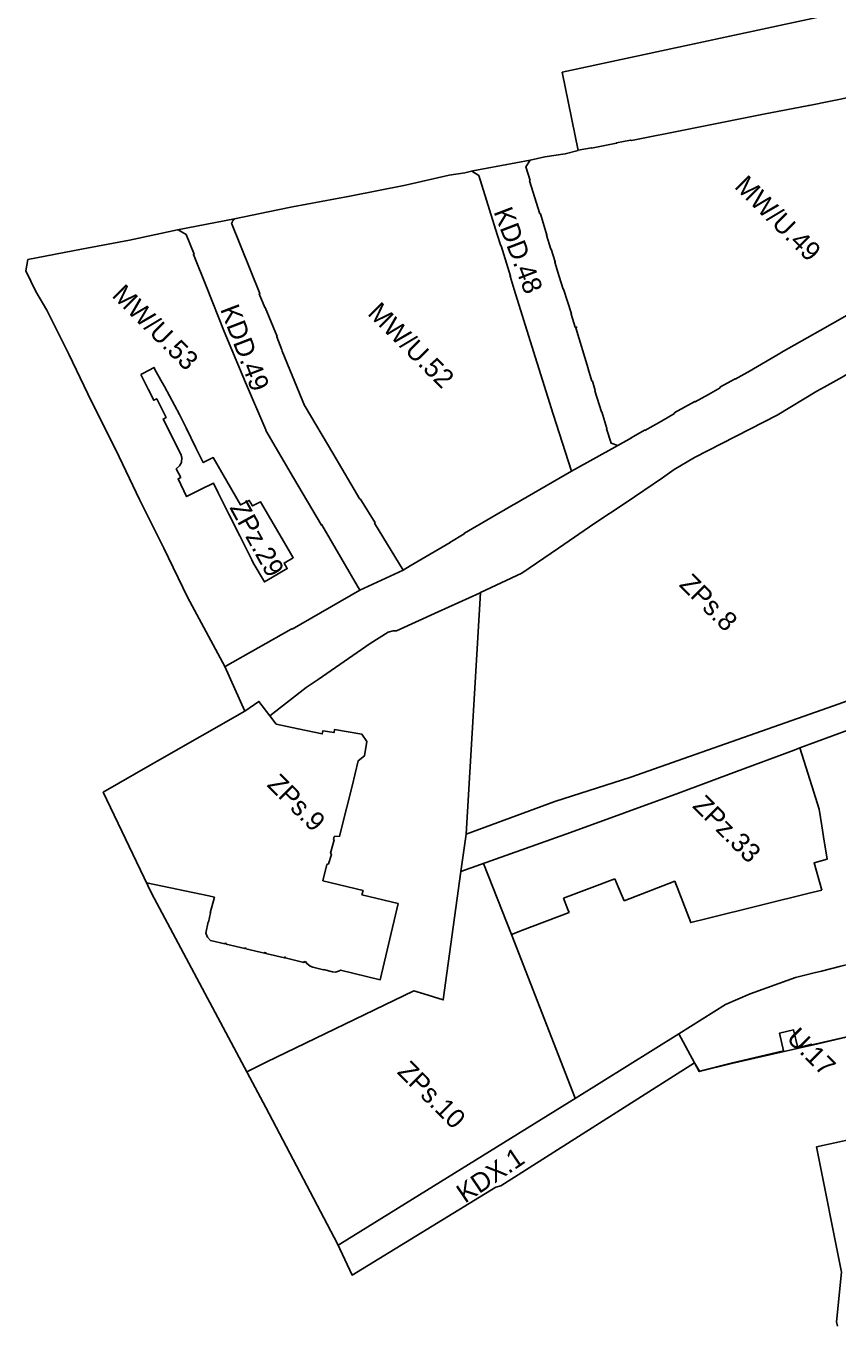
# Model space of a CAD drawing. Extents: x 7423835 to 7425280, y 5546086 to 5547600.
# Drawn here: x 7423835.1 to 7424089, y 5546198.3 to 5546605 of the extents above; entities that cross this region are included whole.
import ezdxf

# ---------------------------------------------------------------- set-up
doc = ezdxf.new("R2010")
doc.units = 0
for name, color, linetype in [('linie rozgraniczające', 7, 'Continuous'), ('nieprzekraczalne linie zabudowy', 7, 'Continuous'), ('obowiazujace linie zabudowy', 7, 'Continuous'), ('przeznaczenia terenów', 7, 'Continuous')]:
    doc.layers.add(name, color=color, linetype=linetype)

msp = doc.modelspace()

# ---------------------------------------------------------------- linework, layer by layer
at = {"layer": 'linie rozgraniczające'}
for p, q in [((7424002.95, 5546590.54), (7424101.85, 5546611.78)), ((7424007.94, 5546566.05), (7424002.95, 5546590.54)), ((7424005.85, 5546465.72), (7424020.34, 5546473.74)), ((7423939.54, 5546428.46), (7423953.14, 5546434.8)), ((7423897.44, 5546404.64), (7423897.34, 5546404.59)), ((7424077.32, 5546379.16), (7424075.54, 5546378.49)), ((7423987.03, 5546320.75), (7423978.35, 5546342.99)), ((7424006.98, 5546269.52), (7423987.03, 5546320.75)), ((7424044.41, 5546280.59), (7424039.51, 5546289.67)), ((7424007.29, 5546269.71), (7423933.34, 5546223.86)), ((7423933.34, 5546223.86), (7423932.8, 5546223.54))]:
    msp.add_line(p, q, dxfattribs=at)
for points in [[(7424007.92, 5546566.13), (7424007.92, 5546566.13), (7424012.08, 5546566.94), (7424012.12, 5546566.8), (7424019.99, 5546568.34), (7424019.98, 5546568.48), (7424024.36, 5546569.34), (7424024.63, 5546569.25), (7424042.46, 5546572.74), (7424065.98, 5546577.41), (7424080.17, 5546580.17), (7424080.29, 5546580.16), (7424093.65, 5546582.86), (7424110.6, 5546586.22), (7424110.68, 5546586.29), (7424125.36, 5546591.15), (7424125.56, 5546591.27), (7424140.15, 5546601.52), (7424140.07, 5546601.67), (7424144.53, 5546604.8)], [(7424091.83, 5546288.66), (7424081.26, 5546286.15), (7424076.53, 5546285.07), (7424071.54, 5546283.94), (7424056.01, 5546280.41), (7424045.88, 5546277.87), (7424044.41, 5546280.59), (7423983.72, 5546242.11), (7423982.18, 5546241.75), (7423937.14, 5546214.2), (7423932.61, 5546223.95), (7423910.19, 5546266.66), (7423874.37, 5546333.67), (7423859.24, 5546365.27), (7423873.99, 5546373.73), (7423876.16, 5546374.97), (7423903.56, 5546390.64), (7423897.35, 5546404.58), (7423885.67, 5546426.36), (7423878.26, 5546441.63), (7423870.62, 5546456.9), (7423863.21, 5546472.44), (7423855.6, 5546487.51), (7423848.47, 5546502.36), (7423841.57, 5546516.12), (7423838.18, 5546521.94), (7423835.06, 5546528.47), (7423835.65, 5546531.92), (7423852.44, 5546535.15), (7423867.52, 5546538.02), (7423882.5, 5546541.21), (7423900.36, 5546544.64), (7423913.95, 5546547.52), (7423918.55, 5546548.42), (7423936.42, 5546551.83), (7423953.84, 5546555.27), (7423967.51, 5546558.31), (7423972.43, 5546559.13), (7423974.95, 5546559.68), (7423992.97, 5546563.05), (7423997.49, 5546564.05), (7424003.93, 5546565.01), (7424007.94, 5546566.05)], [(7423992.87, 5546563.03), (7423991.54, 5546561), (7423992.91, 5546556.69), (7423992.75, 5546556.62), (7423995.97, 5546546.27), (7423996.12, 5546546.3), (7423998.19, 5546539.63), (7423998.04, 5546539.59), (7423999.39, 5546535.2), (7423999.53, 5546535.23), (7424000.77, 5546531.23), (7424000.62, 5546531.18), (7424002.02, 5546526.65), (7424003.26, 5546522.68), (7424003.39, 5546522.7), (7424005.84, 5546514.93), (7424005.71, 5546514.87), (7424006.98, 5546510.75), (7424007.39, 5546510.87), (7424007.47, 5546510.62), (7424007.2, 5546510.54), (7424011.13, 5546497.85), (7424011.05, 5546497.8), (7424012.24, 5546493.91), (7424012.4, 5546493.95), (7424013.31, 5546490.98), (7424013.2, 5546490.9), (7424015.24, 5546484.27), (7424015.41, 5546484.33), (7424016.97, 5546479.08), (7424016.84, 5546479.03), (7424018.25, 5546474.51), (7424020.34, 5546473.74)], [(7423974.7, 5546559.63), (7423976.9, 5546558.21), (7423982.6, 5546539.81), (7423983.71, 5546536.19), (7423983.86, 5546536.24), (7423986.79, 5546526.79), (7423986.64, 5546526.75), (7423987.92, 5546522.6), (7423993.46, 5546504.88), (7424000.11, 5546483.56), (7424005.85, 5546465.72), (7423987.99, 5546455.41), (7423987.81, 5546455.33), (7423987.65, 5546455.24), (7423972.41, 5546446.36), (7423972.3, 5546446.13), (7423967.77, 5546443.47), (7423967.84, 5546443.37), (7423967.84, 5546443.37), (7423961.59, 5546439.73), (7423955.35, 5546436.09), (7423953.14, 5546434.8), (7423944.22, 5546449.45), (7423944.35, 5546449.61), (7423940.15, 5546456.46), (7423939.73, 5546457.09)], [(7423939.73, 5546457.09), (7423939.62, 5546457.02), (7423931.12, 5546471.4), (7423922.43, 5546485.98), (7423922.28, 5546486.32), (7423915.3, 5546503.3), (7423915.17, 5546503.66), (7423913.56, 5546507.77), (7423913.67, 5546507.85), (7423909.99, 5546516.98), (7423909.86, 5546516.94), (7423908.11, 5546521.26), (7423908.28, 5546521.34), (7423899.46, 5546543.38), (7423899.59, 5546543.44), (7423899.67, 5546544.03)], [(7423900.15, 5546544.6), (7423900.12, 5546544.42), (7423899.81, 5546544.21), (7423899.67, 5546544.03)], [(7423882.74, 5546541.26), (7423885.24, 5546539.77), (7423887.67, 5546533.63), (7423887.51, 5546533.57), (7423891.59, 5546523.4), (7423897.15, 5546509.47), (7423903.84, 5546493.45), (7423910.13, 5546478.69), (7423910.19, 5546478.47), (7423918.77, 5546463.62), (7423927.54, 5546448.86), (7423927.72, 5546448.95), (7423939.54, 5546428.46), (7423918.37, 5546416.31), (7423918.29, 5546416.45), (7423918.09, 5546416.31), (7423897.44, 5546404.64)], [(7424095.99, 5546516.73), (7424083.68, 5546509.71), (7424071.51, 5546502.83), (7424071.39, 5546502.79), (7424061.02, 5546496.74), (7424060.84, 5546496.63), (7424057.15, 5546494.55), (7424057.08, 5546494.68), (7424052.31, 5546491.97), (7424052.38, 5546491.83), (7424048.71, 5546489.76), (7424044.58, 5546487.43), (7424044.51, 5546487.56), (7424038.05, 5546483.96), (7424038.13, 5546483.8), (7424034.04, 5546481.4), (7424028.82, 5546478.49), (7424028.72, 5546478.61), (7424024.56, 5546476.22), (7424024.61, 5546476.12), (7424020.34, 5546473.74)], [(7424097.06, 5546498.96), (7424090.64, 5546495.12), (7424084.98, 5546492.05), (7424082.63, 5546490.76), (7424070.3, 5546483.21), (7424044.42, 5546470.01), (7424038.04, 5546466.26), (7424034.35, 5546463.61), (7424022.62, 5546455.76), (7424013.13, 5546449.48), (7424001.74, 5546441.67), (7423990.34, 5546433.85), (7423977.36, 5546427.73)], [(7423977.36, 5546427.73), (7423977.08, 5546427.6), (7423964.07, 5546421.71), (7423951.06, 5546415.82), (7423949.98, 5546415.78), (7423948.42, 5546415.34), (7423942.83, 5546411.83), (7423926.5, 5546400.57), (7423922.81, 5546398.02), (7423911.44, 5546389.18), (7423907.98, 5546393.72), (7423903.56, 5546390.64)], [(7423977.36, 5546427.73), (7423972.84, 5546352.13), (7423971.23, 5546340.47), (7423965.69, 5546300.29), (7423959.65, 5546302.17), (7423956.5, 5546303.15), (7423910.29, 5546280.84), (7423904.22, 5546277.82)], [(7424123.96, 5546405.23), (7424123.96, 5546405.23), (7424105.94, 5546398.77), (7424087.91, 5546392.31), (7424065.35, 5546384.38), (7424042.79, 5546376.46), (7424024.48, 5546370.04), (7424000.69, 5546362.42), (7423972.84, 5546352.13)], [(7424138.23, 5546400.01), (7424137.62, 5546399.74), (7424137.83, 5546399.27), (7424135.32, 5546398.4), (7424132.36, 5546397.54), (7424127.09, 5546395.77), (7424126.8, 5546396.9), (7424116.46, 5546393.29), (7424116.43, 5546393.51), (7424115.71, 5546393.26), (7424115.66, 5546393.41), (7424113.17, 5546392.51), (7424113.2, 5546392.36), (7424077.32, 5546379.16)], [(7423971.23, 5546340.47), (7424005.6, 5546352.64), (7424039.41, 5546364.95), (7424057.48, 5546371.72), (7424075.54, 5546378.49)], [(7424077.32, 5546379.16), (7424081.13, 5546367.24), (7424083.45, 5546360.01), (7424084.26, 5546354.81), (7424084.81, 5546351.33), (7424085.87, 5546344.37)], [(7424085.87, 5546344.37), (7424081.82, 5546343.17), (7424084.22, 5546334.64)], [(7424019.38, 5546338.16), (7424003.39, 5546332.11), (7424003.39, 5546332.11)], [(7424022.34, 5546331.28), (7424020.46, 5546335.65), (7424019.38, 5546338.16)], [(7424022.34, 5546331.28), (7424038.17, 5546337.44), (7424043.19, 5546324.52), (7424048.38, 5546325.8)], [(7424005.11, 5546327.67), (7424004.75, 5546328.6), (7424003.39, 5546332.11)], [(7424084.22, 5546334.64), (7424081.15, 5546333.88), (7424048.38, 5546325.8)], [(7424005.11, 5546327.67), (7423990.55, 5546322.1), (7423987.03, 5546320.75)], [(7424115.02, 5546316.87), (7424109.46, 5546315.54), (7424103.89, 5546314.21), (7424101.84, 5546313.69), (7424096.03, 5546312.29), (7424090.22, 5546310.9), (7424084.12, 5546309.33), (7424081.83, 5546308.77), (7424078.92, 5546308.05), (7424076, 5546307.33), (7424061.81, 5546302.23), (7424054.03, 5546298.9), (7424039.51, 5546289.67), (7424007.29, 5546269.71)], [(7424055.9, 5546280.49), (7424072.29, 5546284.37), (7424070.97, 5546289.86), (7424075.39, 5546290.94), (7424076.76, 5546285.36)], [(7424076.76, 5546285.36), (7424081.09, 5546286.44), (7424081.14, 5546286.23), (7424092.06, 5546288.77)], [(7424044.41, 5546280.59), (7424045.95, 5546278), (7424055.9, 5546280.49)], [(7424089.18, 5546198.28), (7424088.86, 5546199.57), (7424090.45, 5546215.13), (7424082.61, 5546254.35), (7424099.79, 5546258.14)]]:
    msp.add_lwpolyline(points, dxfattribs=at)
msp.add_lwpolyline([(7423871.05, 5546495.97), (7423871.64, 5546496.28), (7423875.16, 5546498.22), (7423875.44, 5546497.58), (7423877.7, 5546493.47), (7423878.4, 5546492.19), (7423883.11, 5546483.47), (7423883.46, 5546482.88), (7423885.26, 5546479.31), (7423885.26, 5546479.31), (7423888.29, 5546473.05), (7423890.54, 5546468.44), (7423893.7, 5546469.98), (7423902.18, 5546455.19), (7423904.96, 5546456.58), (7423906.02, 5546454.85), (7423908.5, 5546456.14), (7423917.45, 5546440.83), (7423918.75, 5546438.65), (7423915.86, 5546436.99), (7423916.86, 5546435.25), (7423912.27, 5546432.58), (7423909.7, 5546431.08), (7423906.24, 5546437.02), (7423905.73, 5546438.02), (7423901.99, 5546445.51), (7423898.6, 5546452.26), (7423898.14, 5546453.17), (7423895.25, 5546458.98), (7423893.75, 5546461.99), (7423889.71, 5546459.97), (7423885.36, 5546457.79), (7423882.66, 5546463.35), (7423883.52, 5546463.77), (7423882.13, 5546466.51), (7423883.1, 5546467.37), (7423883.71, 5546468.48), (7423883.83, 5546469.98), (7423883.53, 5546471.03), (7423877.97, 5546482.05), (7423878.93, 5546482.52), (7423876, 5546488.4), (7423875.09, 5546487.94), (7423873.34, 5546491.41)], close=True, dxfattribs=at)
at = {"layer": 'nieprzekraczalne linie zabudowy'}
msp.add_line((7423945.98, 5546306.62), (7423951.54, 5546330.44), dxfattribs=at)
for points in [[(7423911.44, 5546389.18), (7423907.98, 5546393.72), (7423903.56, 5546390.64)], [(7423911.44, 5546389.18), (7423913.44, 5546386.56)], [(7423928.03, 5546337.54), (7423929.3, 5546342.66), (7423929.82, 5546342.91), (7423930.67, 5546345.85), (7423930.41, 5546346.22), (7423931.6, 5546350.44), (7423931.35, 5546350.51), (7423931.59, 5546351.42), (7423933.23, 5546351.51), (7423935.52, 5546360.58), (7423937.2, 5546367.19), (7423939.08, 5546375.12), (7423941.03, 5546376.66), (7423941.81, 5546381.18), (7423940.25, 5546383.45), (7423931.65, 5546384.89), (7423931.54, 5546383.94), (7423928.01, 5546384.54), (7423927.82, 5546383.53), (7423920.26, 5546385.12), (7423913.44, 5546386.56)], [(7423872.83, 5546336.89), (7423892.3, 5546332.89), (7423894.05, 5546332.42)], [(7423940.26, 5546333.14), (7423940.26, 5546333.14), (7423940.26, 5546333.14), (7423940.6, 5546334.56), (7423928.03, 5546337.54)], [(7423894.05, 5546332.42), (7423894.05, 5546332.42), (7423894.05, 5546332.42), (7423892.76, 5546327.52), (7423892.82, 5546327.5), (7423892.22, 5546324.68), (7423892.08, 5546324.71), (7423891.36, 5546321.19), (7423891.91, 5546319.97), (7423892.88, 5546318.86), (7423897.33, 5546317.82), (7423897.4, 5546318.05), (7423897.83, 5546317.95), (7423897.79, 5546317.73), (7423903.56, 5546316.34), (7423903.62, 5546316.6), (7423903.98, 5546316.52), (7423903.93, 5546316.33), (7423909.72, 5546314.91), (7423909.79, 5546315.17), (7423910.19, 5546315.08), (7423910.15, 5546314.86), (7423915.98, 5546313.46), (7423916.04, 5546313.72), (7423916.27, 5546313.66), (7423916.22, 5546313.46), (7423922.08, 5546312), (7423922.15, 5546312.28), (7423922.81, 5546312.12), (7423922.9, 5546311.78), (7423924.02, 5546310.87), (7423924.85, 5546310.55), (7423928.2, 5546309.74), (7423928.22, 5546309.82), (7423930.98, 5546309.11), (7423932.01, 5546308.95), (7423933.25, 5546309.36), (7423933.5, 5546309.59), (7423933.5, 5546309.59)], [(7423951.54, 5546330.44), (7423951.54, 5546330.44), (7423951.54, 5546330.44), (7423940.26, 5546333.14), (7423940.26, 5546333.14), (7423940.26, 5546333.14), (7423940.26, 5546333.14), (7423940.26, 5546333.14)], [(7423933.5, 5546309.59), (7423945.98, 5546306.62), (7423945.98, 5546306.62), (7423945.98, 5546306.62), (7423945.98, 5546306.62), (7423945.98, 5546306.62)]]:
    msp.add_lwpolyline(points, dxfattribs=at)
at = {"layer": 'obowiazujace linie zabudowy'}
for points in [[(7424144.53, 5546604.8), (7424140.07, 5546601.67), (7424140.15, 5546601.52), (7424125.56, 5546591.27), (7424125.36, 5546591.15), (7424110.68, 5546586.29), (7424110.6, 5546586.22), (7424093.65, 5546582.86), (7424080.29, 5546580.16), (7424080.17, 5546580.17), (7424065.98, 5546577.41), (7424042.46, 5546572.74), (7424024.63, 5546569.25), (7424024.36, 5546569.34), (7424019.98, 5546568.48), (7424019.99, 5546568.34), (7424012.12, 5546566.8), (7424012.08, 5546566.94), (7424007.92, 5546566.13), (7424007.92, 5546566.13)], [(7423992.87, 5546563.03), (7423991.54, 5546561), (7423992.91, 5546556.69), (7423992.75, 5546556.62), (7423995.97, 5546546.27), (7423996.12, 5546546.3), (7423998.19, 5546539.63), (7423998.04, 5546539.59), (7423999.39, 5546535.2), (7423999.53, 5546535.23), (7424000.77, 5546531.23), (7424000.62, 5546531.18), (7424002.02, 5546526.65), (7424003.26, 5546522.68), (7424003.39, 5546522.7), (7424005.84, 5546514.93), (7424005.71, 5546514.87), (7424006.98, 5546510.75), (7424007.39, 5546510.87), (7424007.47, 5546510.62), (7424007.2, 5546510.54), (7424011.13, 5546497.85), (7424011.05, 5546497.8), (7424012.24, 5546493.91), (7424012.4, 5546493.95), (7424013.31, 5546490.98), (7424013.2, 5546490.9), (7424015.24, 5546484.27), (7424015.41, 5546484.33), (7424016.97, 5546479.08), (7424016.84, 5546479.03), (7424018.25, 5546474.51), (7424020.34, 5546473.74)], [(7424007.94, 5546566.05), (7424003.93, 5546565.01), (7423997.49, 5546564.05), (7423992.97, 5546563.05), (7423992.87, 5546563.03)], [(7423974.95, 5546559.68), (7423972.43, 5546559.13), (7423967.51, 5546558.31), (7423953.84, 5546555.27), (7423936.42, 5546551.83), (7423918.55, 5546548.42), (7423913.95, 5546547.52), (7423900.36, 5546544.64)], [(7423939.73, 5546457.09), (7423940.15, 5546456.46), (7423944.35, 5546449.61), (7423944.22, 5546449.45), (7423953.14, 5546434.8), (7423955.35, 5546436.09), (7423961.59, 5546439.73), (7423967.84, 5546443.37), (7423967.84, 5546443.37), (7423967.77, 5546443.47), (7423972.3, 5546446.13), (7423972.41, 5546446.36), (7423987.65, 5546455.24), (7423987.81, 5546455.33), (7423987.99, 5546455.41), (7424005.85, 5546465.72), (7424000.11, 5546483.56), (7423993.46, 5546504.88), (7423987.92, 5546522.6), (7423986.64, 5546526.75), (7423986.79, 5546526.79), (7423983.86, 5546536.24), (7423983.71, 5546536.19), (7423982.6, 5546539.81), (7423976.9, 5546558.21), (7423974.7, 5546559.63)], [(7423899.67, 5546544.03), (7423899.59, 5546543.44), (7423899.46, 5546543.38), (7423908.28, 5546521.34), (7423908.11, 5546521.26), (7423909.86, 5546516.94), (7423909.99, 5546516.98), (7423913.67, 5546507.85), (7423913.56, 5546507.77), (7423915.17, 5546503.66), (7423915.3, 5546503.3), (7423922.28, 5546486.32), (7423922.43, 5546485.98), (7423931.12, 5546471.4), (7423939.62, 5546457.02), (7423939.73, 5546457.09)], [(7423882.74, 5546541.26), (7423882.5, 5546541.21), (7423867.52, 5546538.02), (7423852.44, 5546535.15), (7423835.65, 5546531.92), (7423835.06, 5546528.47), (7423838.18, 5546521.94), (7423841.57, 5546516.12), (7423848.47, 5546502.36), (7423855.6, 5546487.51), (7423863.21, 5546472.44), (7423870.62, 5546456.9), (7423878.26, 5546441.63), (7423885.67, 5546426.36), (7423897.35, 5546404.59)], [(7423897.44, 5546404.64), (7423918.09, 5546416.31), (7423918.29, 5546416.45), (7423918.37, 5546416.31), (7423939.54, 5546428.46), (7423927.72, 5546448.95), (7423927.54, 5546448.86), (7423918.77, 5546463.62), (7423910.19, 5546478.47), (7423910.13, 5546478.69), (7423903.84, 5546493.45), (7423897.15, 5546509.47), (7423891.59, 5546523.4), (7423887.51, 5546533.57), (7423887.67, 5546533.63), (7423885.24, 5546539.77), (7423882.74, 5546541.26)], [(7424020.34, 5546473.74), (7424024.61, 5546476.12), (7424024.56, 5546476.22), (7424028.72, 5546478.61), (7424028.82, 5546478.49), (7424034.04, 5546481.4), (7424038.13, 5546483.8), (7424038.05, 5546483.96), (7424044.51, 5546487.56), (7424044.58, 5546487.43), (7424048.71, 5546489.76), (7424052.38, 5546491.83), (7424052.31, 5546491.97), (7424057.08, 5546494.68), (7424057.15, 5546494.55), (7424060.84, 5546496.63), (7424061.02, 5546496.74), (7424071.39, 5546502.79), (7424071.51, 5546502.83), (7424083.68, 5546509.71), (7424095.99, 5546516.73)], [(7424138.23, 5546400.01), (7424137.62, 5546399.74), (7424137.83, 5546399.27), (7424135.32, 5546398.4), (7424132.36, 5546397.54), (7424127.09, 5546395.77), (7424126.8, 5546396.9), (7424116.46, 5546393.29), (7424116.43, 5546393.51), (7424115.71, 5546393.26), (7424115.66, 5546393.41), (7424113.17, 5546392.51), (7424113.2, 5546392.36), (7424077.32, 5546379.16)], [(7424007.29, 5546269.71), (7424039.51, 5546289.67), (7424054.03, 5546298.9), (7424061.81, 5546302.23), (7424076, 5546307.33), (7424078.92, 5546308.05), (7424081.83, 5546308.77), (7424084.12, 5546309.33), (7424090.22, 5546310.9), (7424096.03, 5546312.29), (7424101.84, 5546313.69), (7424103.89, 5546314.21), (7424109.46, 5546315.54), (7424115.02, 5546316.87)], [(7424076.76, 5546285.36), (7424075.39, 5546290.94), (7424070.97, 5546289.86), (7424072.29, 5546284.37), (7424055.9, 5546280.49)], [(7424092.06, 5546288.77), (7424081.14, 5546286.23), (7424081.09, 5546286.44), (7424076.76, 5546285.36)], [(7424055.9, 5546280.49), (7424045.95, 5546278), (7424044.41, 5546280.59)]]:
    msp.add_lwpolyline(points, dxfattribs=at)

# ---------------------------------------------------------------- texts
at = {"layer": 'przeznaczenia terenów'}
for s, rotation, p in [('MW/U.49', 314.9764, (7424056.59, 5546554.58)), ('KDD.48', 290.9511, (7423981.39, 5546546.92)), ('MW/U.53', 314.9764, (7423861.66, 5546520.5)), ('MW/U.52', 314.9764, (7423941.75, 5546514.86)), ('KDD.49', 290.9511, (7423895.8, 5546516.44)), ('ZPz.29', 298.825, (7423898.67, 5546454.33)), ('ZPs.8', 314.9764, (7424039.3, 5546429.98)), ('ZPs.9', 314.9764, (7423910.25, 5546367.36)), ('ZPz.33', 314.9764, (7424043.47, 5546360.71)), ('U.17', 314.9764, (7424072.87, 5546287.98)), ('ZPs.10', 314.9764, (7423951.02, 5546277.51)), ('KDX.1', 34.1784, (7423972.51, 5546236.51))]:
    msp.add_text(s, height=6, rotation=rotation, dxfattribs=at).set_placement(p)

doc.saveas('drawing.dxf')
